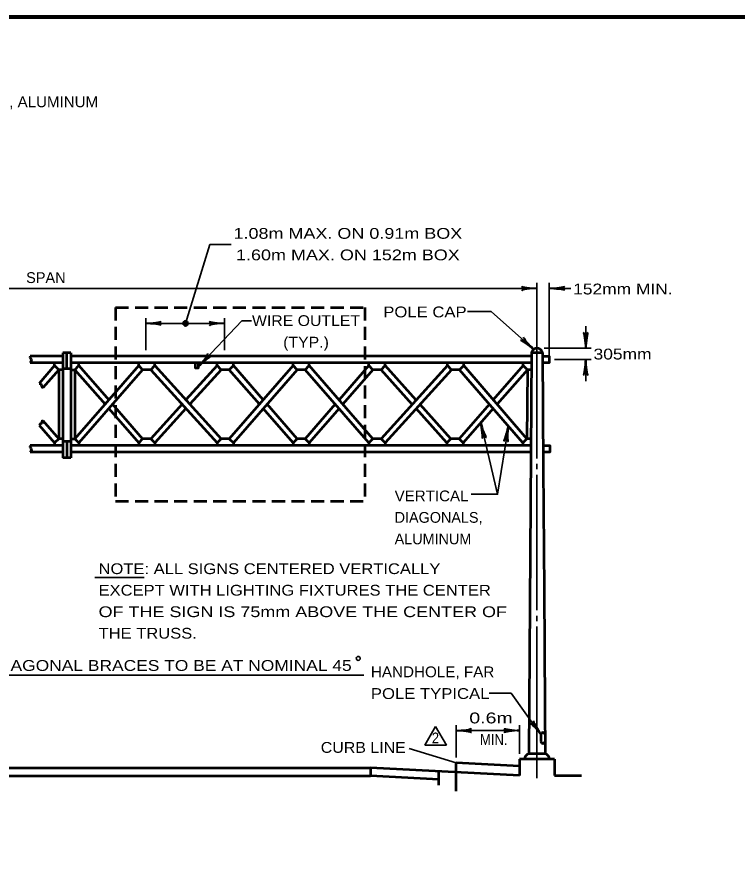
# Model space of a CAD drawing. Extents: x -29 to 827, y -14 to 530.
# Drawn here: x 296.8 to 457.6, y 336.4 to 523.3 of the extents above; entities that cross this region are included whole.
import ezdxf
from ezdxf.enums import TextEntityAlignment as Align

# ---------------------------------------------------------------- set-up
doc = ezdxf.new("R2010")
doc.units = 0
doc.header["$LTSCALE"] = 0.97
doc.linetypes.add('MEDIUM_DASHED', pattern=[4.5, 3, -1.5])
doc.layers.add('1', color=7, linetype='Continuous', lineweight=53)

msp = doc.modelspace()

# ---------------------------------------------------------------- hatches: boundary and pattern name
at = {"layer": '1'}
msp.add_hatch(color=256, dxfattribs=at).paths.add_polyline_path([(335.0798, 454.8263, 1), (333.8998, 454.8263, 1)])

# ---------------------------------------------------------------- linework, layer by layer
at = {"layer": '1', "lineweight": 35}
for p, q in [((415.6315, 447.5085), (415.6315, 463.8525)), ((181.3915, 462.6285), (412.9195, 462.6285)), ((415.6315, 462.6285), (420.4795, 462.6285)), ((325.6008, 448.8263), (325.6008, 456.0263)), ((325.6008, 454.8263), (343.21, 454.8263)), ((343.21, 448.8263), (343.21, 456.0263)), ((423.8155, 449.3325), (423.8155, 454.1805)), ((414.5515, 449.3325), (425.0155, 449.3325)), ((416.8555, 446.7645), (425.0155, 446.7645)), ((423.8155, 446.7645), (423.8155, 441.9165)), ((412.9195, 422.2605), (412.9195, 423.4845)), ((412.9195, 390.8205), (412.9195, 421.0605)), ((404.1542, 416.7027), (398.2337, 416.7027)), ((314.2446, 398.1088), (325.2269, 398.1088)), ((412.9195, 388.3965), (412.9195, 389.5965)), ((412.9195, 353.3085), (412.9195, 387.1965)), ((282.2798, 376.3432), (374.2761, 376.3432)), ((407.1502, 372.2815), (402.2302, 372.2815)), ((413.8048, 363.0408), (407.1502, 372.2815)), ((390.3035, 364.8507), (387.9035, 360.6938)), ((390.3035, 364.8507), (392.7035, 360.6938)), ((394.8869, 357.9802), (394.8869, 365.1627)), ((409.0075, 358.7565), (409.0075, 365.1627)), ((394.8869, 363.9627), (409.0075, 363.9627)), ((394.8869, 356.7802), (384.4092, 359.926)), ((392.7035, 360.6938), (387.9035, 360.6938))]:
    msp.add_line(p, q, dxfattribs=at)
at = {"layer": '1', "linetype": 'MEDIUM_DASHED'}
for p, q in [((318.8635, 458.4045), (318.8635, 415.1565)), ((318.8635, 458.4045), (374.5195, 458.4045)), ((374.5195, 458.4045), (374.5195, 415.1565)), ((318.8635, 415.1565), (374.5195, 415.1565))]:
    msp.add_line(p, q, dxfattribs=at)
at = {"layer": '1'}
for p, q in [((307.0795, 447.5085), (299.8315, 447.5085)), ((307.0795, 448.2765), (307.0795, 424.8285)), ((308.9035, 448.2765), (307.0795, 448.2765)), ((307.9915, 444.6525), (307.9915, 448.2765)), ((308.9035, 448.2765), (308.9035, 424.8285)), ((411.7195, 447.5085), (308.9035, 447.5085)), ((411.7195, 448.2765), (411.1195, 358.7565)), ((414.1435, 448.2765), (411.7195, 448.2765)), ((307.0795, 445.9965), (299.8315, 445.9965)), ((305.2555, 445.3965), (301.7995, 441.4125)), ((305.2555, 445.3965), (305.2555, 445.9965)), ((306.1675, 444.4845), (305.2555, 445.3965)), ((310.7035, 445.9965), (308.9035, 445.9965)), ((309.7915, 444.4845), (310.7035, 445.3965)), ((324.0235, 445.3965), (309.7915, 429.0765)), ((310.7035, 445.3965), (310.7035, 445.9965)), ((310.7035, 445.3965), (317.3515, 437.7645)), ((324.0235, 445.3965), (324.0235, 445.9965)), ((324.9115, 444.4845), (324.0235, 445.3965)), ((326.7355, 444.4845), (327.6475, 445.3965)), ((327.6475, 445.3965), (327.6475, 445.9965)), ((327.6475, 445.3965), (342.4555, 429.0765)), ((341.5435, 445.3965), (334.5835, 437.7405)), ((341.5435, 445.3965), (341.5435, 445.9965)), ((342.4555, 444.4845), (341.5435, 445.3965)), ((344.2555, 444.4845), (345.1675, 445.3965)), ((358.4875, 445.3965), (344.2555, 429.0765)), ((345.1675, 445.3965), (345.1675, 445.9965)), ((351.8155, 437.7645), (345.1675, 445.3965)), ((358.4875, 445.3965), (358.4875, 445.9965)), ((362.1115, 445.9965), (358.4875, 445.9965)), ((359.3755, 444.4845), (358.4875, 445.3965)), ((361.1995, 444.4845), (362.1115, 445.3965)), ((362.1115, 445.3965), (362.1115, 445.9965)), ((376.3195, 429.0765), (362.1115, 445.3965)), ((375.4075, 445.3965), (368.7595, 437.7645)), ((375.4075, 445.3965), (375.4075, 445.9965)), ((376.3195, 444.4845), (375.4075, 445.3965)), ((378.1435, 444.4845), (379.0315, 445.3965)), ((392.9515, 445.3965), (378.1435, 429.0765)), ((379.0315, 445.3965), (379.0315, 445.9965)), ((385.9675, 437.6925), (379.0315, 445.3965)), ((392.9515, 445.3965), (392.9515, 445.9965)), ((393.8635, 444.4845), (392.9515, 445.3965)), ((395.6635, 444.4845), (396.5755, 445.3965)), ((396.5755, 445.3965), (396.5755, 445.9965)), ((410.6635, 429.0765), (396.5755, 445.3965)), ((409.8715, 445.3965), (403.1755, 437.7645)), ((409.8715, 445.3965), (409.8715, 445.9965)), ((410.7835, 444.4845), (409.8715, 445.3965)), ((306.1675, 444.4845), (302.6395, 440.4285)), ((306.1675, 444.4845), (306.1675, 429.0765)), ((307.0795, 444.4845), (306.1675, 444.4845)), ((308.9035, 444.6525), (307.0795, 444.6525)), ((308.9035, 444.4845), (309.7915, 444.4845)), ((309.7915, 444.4845), (309.7915, 429.0765)), ((309.7915, 444.4845), (316.5115, 436.7805)), ((324.9115, 444.4845), (310.7035, 428.1645)), ((326.7355, 444.4845), (341.5435, 428.1645)), ((342.4555, 444.4845), (335.4475, 436.7805)), ((350.9755, 436.7805), (344.2555, 444.4845)), ((359.3755, 444.4845), (345.1675, 428.1645)), ((375.4075, 428.1645), (361.1995, 444.4845)), ((376.3195, 444.4845), (369.5995, 436.7805)), ((385.1035, 436.7565), (378.1435, 444.4845)), ((393.8635, 444.4845), (379.0315, 428.1645)), ((409.7515, 428.1645), (395.6635, 444.4845)), ((410.7835, 444.4845), (404.0155, 436.7805)), ((410.7835, 444.4845), (410.6635, 429.0765)), ((411.6955, 444.4845), (410.7835, 444.4845)), ((317.3515, 435.7965), (324.0235, 428.1645)), ((318.2155, 436.7805), (324.9115, 429.0765)), ((333.7195, 436.7805), (326.7355, 429.0765)), ((334.5835, 435.8205), (327.6475, 428.1645)), ((358.4875, 428.1645), (351.8155, 435.7965)), ((359.3755, 429.0765), (352.6795, 436.7805)), ((367.9195, 436.7805), (361.1995, 429.0765)), ((368.7595, 435.7965), (362.1115, 428.1645)), ((392.8315, 428.1645), (385.9675, 435.7965)), ((393.7195, 429.0765), (386.8315, 436.7565)), ((402.3115, 436.7805), (395.5435, 429.0765)), ((403.1515, 435.7965), (396.4555, 428.1645)), ((301.7995, 432.1485), (305.2555, 428.1645)), ((302.6395, 433.1325), (306.1675, 429.0765)), ((306.1675, 429.0765), (305.2555, 428.1645)), ((305.2555, 428.1645), (305.2555, 427.5645)), ((307.0795, 429.0765), (306.1675, 429.0765)), ((308.9035, 428.4765), (307.0795, 428.4765)), ((307.9915, 428.4765), (307.9915, 424.8285)), ((308.9035, 429.0765), (309.7915, 429.0765)), ((309.7915, 429.0765), (310.7035, 428.1645)), ((310.7035, 428.1645), (310.7035, 427.5645)), ((324.9115, 429.0765), (324.0235, 428.1645)), ((324.0235, 428.1645), (324.0235, 427.5645)), ((326.7355, 429.0765), (324.9115, 429.0765)), ((326.7355, 429.0765), (327.6475, 428.1645)), ((327.6475, 428.1645), (327.6475, 427.5645)), ((342.4555, 429.0765), (341.5435, 428.1645)), ((341.5435, 428.1645), (341.5435, 427.5645)), ((344.2555, 429.0765), (342.4555, 429.0765)), ((344.2555, 429.0765), (345.1675, 428.1645)), ((345.1675, 428.1645), (345.1675, 427.5645)), ((359.3755, 429.0765), (358.4875, 428.1645)), ((358.4875, 428.1645), (358.4875, 427.5645)), ((361.1995, 429.0765), (359.3755, 429.0765)), ((361.1995, 429.0765), (362.1115, 428.1645)), ((362.1115, 428.1645), (362.1115, 427.5645)), ((376.3195, 429.0765), (375.4075, 428.1645)), ((375.4075, 428.1645), (375.4075, 427.5645)), ((378.1435, 429.0765), (376.3195, 429.0765)), ((378.1435, 429.0765), (379.0315, 428.1645)), ((379.0315, 428.1645), (379.0315, 427.5645)), ((393.7195, 429.0765), (392.8315, 428.1645)), ((392.8315, 428.1645), (392.8315, 427.5645)), ((395.5435, 429.0765), (393.7195, 429.0765)), ((395.5435, 429.0765), (396.4555, 428.1645)), ((396.4555, 428.1645), (396.4555, 427.5645)), ((410.6635, 429.0765), (409.7515, 428.1645)), ((409.7515, 428.1645), (409.7515, 427.5645)), ((411.5755, 429.0765), (410.6635, 429.0765)), ((307.0795, 427.5645), (299.8315, 427.5645)), ((307.0795, 426.0525), (299.8315, 426.0525)), ((308.9035, 424.8285), (307.0795, 424.8285)), ((411.5515, 426.0525), (308.9035, 426.0525)), ((413.8048, 363.0408), (413.8048, 361.5288)), ((416.8555, 357.5565), (409.0075, 357.5565)), ((409.0075, 357.5565), (409.0075, 353.9325)), ((416.8555, 357.5565), (416.8555, 353.9325)), ((409.0075, 353.9325), (375.7915, 355.6605)), ((375.7915, 355.6605), (375.7915, 353.8605)), ((409.0075, 356.0456), (394.8869, 356.7802)), ((394.8869, 350.4591), (394.8869, 356.7802)), ((218.5435, 353.8605), (375.7915, 353.8605)), ((391.0325, 353.0676), (375.7915, 353.8605)), ((391.0325, 351.8116), (391.0325, 354.8676)), ((416.8555, 353.9325), (422.9035, 353.9325))]:
    msp.add_line(p, q, dxfattribs=at)
at = {"layer": '1', "lineweight": 158}
msp.add_lwpolyline([(820.0407, 523.2545), (28.3407, 523.1545), (28.4407, -2.8455)], dxfattribs=at)
at = {"layer": '1', "lineweight": 35}
for points in [[(334.4898, 454.8263), (339.9352, 472.4249), (344.6628, 472.4249)], [(412.9195, 424.6845), (412.9195, 449.3325), (412.9195, 463.8525)], [(412.1755, 449.0685), (402.6715, 457.4685), (397.4155, 457.4685)], [(337.423, 445.2544), (347.039, 455.3626), (349.1759, 455.3626)], [(400.3811, 432.6389), (404.1542, 416.7027), (406.5427, 431.8816)]]:
    msp.add_lwpolyline(points, dxfattribs=at)
at = {"layer": '1'}
for points in [[(414.1435, 448.2765), (414.3115, 422.5725), (414.5035, 395.3565), (414.6715, 369.3405)], [(414.1435, 447.5085), (415.6315, 447.5085), (415.6315, 445.9965), (414.1435, 445.9965)], [(358.4875, 445.9965), (341.5435, 445.9965), (310.7035, 445.9965)], [(337.3195, 445.9965), (337.3195, 444.7965), (336.6955, 444.7965), (336.6955, 445.9965)], [(411.6955, 445.9965), (409.8715, 445.9965), (362.1115, 445.9965)], [(326.7355, 444.4845), (325.8235, 444.4845), (324.9115, 444.4845)], [(344.2555, 444.4845), (343.3675, 444.4845), (342.4555, 444.4845)], [(361.1995, 444.4845), (360.2875, 444.4845), (359.3755, 444.4845)], [(378.1435, 444.4845), (377.2315, 444.4845), (376.3195, 444.4845)], [(395.6635, 444.4845), (394.7515, 444.4845), (393.8635, 444.4845)], [(362.1115, 427.5645), (358.4875, 427.5645), (310.7035, 427.5645), (308.9035, 427.5645)], [(411.5755, 427.5645), (409.7515, 427.5645), (362.1115, 427.5645)], [(414.2635, 427.5645), (415.7755, 427.5645), (415.7755, 426.0525), (414.2875, 426.0525)], [(414.6715, 369.3405), (414.7435, 358.7565), (411.1195, 358.7565)], [(185.3035, 353.9325), (218.5435, 355.6605), (375.7915, 355.6605)]]:
    msp.add_lwpolyline(points, dxfattribs=at)
at = {"layer": '1', "lineweight": 35}
for centre, radius in [((334.4898, 454.8263), 0.59), ((373.037, 380.066), 0.4355)]:
    msp.add_circle(centre, radius, dxfattribs=at)
at = {"layer": '1'}
for centre, radius, start, end in [((412.931, 448.1113), 1.2204, 7.62224, 172.37776), ((414.256, 363.0484), 0.4536, 0, 180), ((414.256, 361.5364), 0.4536, 180, 0), ((411.2973, 357.6822), 1.0956, 99.49518, 186.76502), ((414.5646, 357.6822), 1.0956, 353.23498, 80.50482)]:
    msp.add_arc(centre, radius, start, end, dxfattribs=at)
at = {"layer": '1', "lineweight": 40}
for centre, major_axis, ratio, start_param, end_param in [((411.6111, 462.303), (2.16, 0.1889), 0.122415, 0.89635335, 3.14159265), ((411.5756, 462.8932), (2.1246, -0.2125), 0.07063, 3.14071475, 5.41810995), ((416.9962, 462.3813), (-2.1246, 0.2125), 0.07063, 3.14071475, 5.41810995), ((416.9608, 462.9714), (-2.16, -0.1889), 0.122415, 0.89635335, 3.14159265), ((326.9454, 454.5724), (-2.1077, 0.2108), 0.07063, 3.14071475, 5.41810995), ((326.9102, 455.1579), (-2.1428, -0.1874), 0.122415, 0.89635335, 3.14159265), ((341.9006, 454.4947), (2.1428, 0.1874), 0.122415, 0.89635335, 3.14159265), ((341.9006, 454.4947), (2.1428, 0.1874), 0.122415, 0.89635335, 3.14159265), ((341.8654, 455.0802), (2.1077, -0.2108), 0.07063, 3.14071475, 5.41810995), ((341.8654, 455.0802), (2.1077, -0.2108), 0.07063, 3.14071475, 5.41810995), ((423.4832, 450.6515), (0.1889, -2.16), 0.122415, 0.89635335, 3.14159265), ((424.0733, 450.687), (-0.2125, -2.1246), 0.07063, 3.14071475, 5.41810995), ((410.9703, 449.6964), (1.7452, -1.2866), 0.122415, 0.89635335, 3.14159265), ((411.3339, 450.1625), (1.4533, -1.5643), 0.07063, 3.14071475, 5.41810995), ((338.0853, 446.4317), (-1.3412, -1.6817), 0.122415, 0.89635335, 3.14159265), ((338.5337, 446.0536), (1.6055, 1.3818), 0.07063, 6.28230741, 8.55970261), ((423.5614, 445.4058), (0.2125, 2.1246), 0.07063, 3.14071475, 5.41810995), ((424.1516, 445.4412), (-0.1889, 2.16), 0.122415, 0.89635335, 3.14159265), ((400.4438, 431.272), (-0.2805, 2.0996), 0.07063, 3.14071475, 5.41810995), ((401.0054, 431.4411), (-0.676, 2.042), 0.122415, 0.89635335, 3.14159265), ((406.0829, 430.5928), (-0.5359, -2.0494), 0.07063, 6.28230741, 8.55970261), ((406.6667, 430.5365), (0.148, 2.1459), 0.122415, 0.89635335, 3.14159265), ((396.1963, 364.2943), (-2.1428, -0.1874), 0.122415, 0.89635335, 3.14159265), ((396.1963, 364.2943), (-2.1428, -0.1874), 0.122415, 0.89635335, 3.14159265), ((396.1963, 364.2943), (-2.1428, -0.1874), 0.122415, 0.89635335, 3.14159265), ((412.7705, 363.9096), (1.4043, -1.6294), 0.122415, 0.89635335, 3.14159265), ((413.2251, 364.2803), (1.0607, -1.8336), 0.07063, 3.14071475, 5.41810995), ((396.2315, 363.7088), (-2.1077, 0.2108), 0.07063, 3.14071475, 5.41810995), ((396.2315, 363.7088), (-2.1077, 0.2108), 0.07063, 3.14071475, 5.41810995), ((396.2315, 363.7088), (-2.1077, 0.2108), 0.07063, 3.14071475, 5.41810995), ((407.6981, 363.6311), (2.1428, 0.1874), 0.122415, 0.89635335, 3.14159265), ((407.6629, 364.2166), (2.1077, -0.2108), 0.07063, 3.14071475, 5.41810995)]:
    msp.add_ellipse(centre, major_axis=major_axis, ratio=ratio, start_param=start_param, end_param=end_param, dxfattribs=at)
at = {"layer": '1'}
for points in [[(299.8315, 447.5085), (299.7595, 447.2205), (299.9755, 446.8845), (300.0715, 446.5245), (299.8795, 446.1885), (299.8315, 445.9965)], [(301.7995, 441.4125), (302.1835, 441.3645), (302.3275, 440.8605), (302.6395, 440.4285)], [(302.6395, 433.1325), (302.3755, 432.8685), (302.5915, 432.6045), (302.2315, 432.4605), (301.7995, 432.1485)], [(299.8315, 427.5645), (299.7595, 427.2765), (299.9755, 426.9405), (300.0715, 426.5805), (299.9035, 426.2445), (299.8315, 426.0525)]]:
    msp.add_spline(points, degree=3, dxfattribs=at)

# ---------------------------------------------------------------- texts
for s, height, width, p in [('HOR. DIAGONALS, ALUMINUM', 2.4, 1.05, (266.1088, 503.0638)), ('152mm MIN.', 2.419, 1.2, (421.0075, 461.2845)), ('POLE CAP', 2.419, 1.15, (378.6235, 456.1701)), ('305mm', 2.419, 1.2, (425.562, 446.7693)), ('VERTICAL', 2.4, 1.05, (381.1605, 415.1291)), ('NOTE: ALL SIGNS CENTERED VERTICALLY', 2.4, 1.15, (315.0707, 398.8767)), ('EXCEPT WITH LIGHTING FIXTURES THE CENTER', 2.4, 1.15, (315.0707, 394.0767)), ('OF THE SIGN IS 75mm ABOVE THE CENTER OF', 2.4, 1.25, (315.0707, 389.2767)), ('THE TRUSS.', 2.4, 1.15, (315.0707, 384.4767)), ('HANDHOLE, FAR', 2.419, 1.05, (375.8567, 375.8535)), ('POLE TYPICAL', 2.419, 1.15, (375.8567, 371.0055)), ('2', 2.4, 0.9, (389.4623, 361.1141)), ('CURB LINE', 2.419, 1.1, (364.6695, 358.9877))]:
    msp.add_text(s, height=height, dxfattribs=dict(at, width=width)).set_placement(p)
for s, height, width, p in [('1.08m MAX. ON 0.91m BOX', 2.4, 1.25, (370.7223, 473.7083)), ('1.60m MAX. ON 152m BOX', 2.4, 1.25, (370.7223, 468.9083)), ('WIRE OUTLET', 2.4, 1.1, (361.3808, 454.2411)), ('(TYP.)', 2.4, 1.1, (361.3808, 449.4411)), ('ALL DIAGONAL BRACES TO BE AT NOMINAL 45', 2.419, 1.2, (327.5638, 377.2728)), ('0.6m ', 2.419, 1.35, (403.2835, 365.5608)), ('MIN.', 2.419, 0.9, (403.2834, 360.7416))]:
    msp.add_text(s, height=height, dxfattribs=dict(at, width=width)).set_placement(p, align=Align.CENTER)
msp.add_text('SPAN', height=2.419, dxfattribs=at).set_placement((303.3123, 463.8326), align=Align.CENTER)
for s, p in [('DIAGONALS,', (381.1605, 410.3291)), ('ALUMINUM', (381.1605, 405.5291))]:
    msp.add_text(s, height=2.4, dxfattribs=at).set_placement(p)

doc.saveas('drawing.dxf')
